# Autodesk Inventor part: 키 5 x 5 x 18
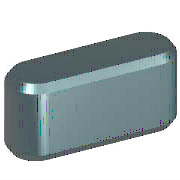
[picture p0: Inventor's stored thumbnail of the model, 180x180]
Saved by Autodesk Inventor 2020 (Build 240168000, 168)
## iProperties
Created: 2012-02
Part Number: 키 5 x 5 x 18
Material: 강철, 연강
Description: 키 및 해당 키홈
Document SubType Name: Modeling
Standard: KS B 1311
Designer: mduedu
Standards Organization: KS
Language: ko-KR
Size Designation: 5 x 5 x 18
Categories: <MemberInstance><Categories><Category DisplayName="샤프트 부품" InternalName="7f7aeb1f-a693-4053-b835-cee3144e0d98" Mnemonic="SHFT"><Category DisplayName="키" Interna
Density: 1 g/cm^3
Appearance: 노란색
IsCustomPart: 1
Author: mduedu
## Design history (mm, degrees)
workplane "Work Plane1"
workplane "Work Plane2"
sketch "스케치1"
  geometry: L1 (2.5, 2.5)-(15.5, 2.5); L2 (15.5, -2.5)-(2.5, -2.5); L3 (0, 9.4)-(0, -7.4) reference; L4 (-5, 0)-(30, 0) reference; L5 (18, 0)-(18, 7); A1 r 2.5 centre (2.5, 0) between (2.5, 2.5) and (2.5, -2.5); A2 r 2.5 centre (15.5, 0) between (15.5, -2.5) and (15.5, 2.5)
  constraints: 6 end point, 5 point on circle, 4 tangent, 3 point on line, 2 centre point, 1 horizontal, 1 parallel, 1 perpendicular
  dimensions: "d0" = 2.5 radius of A1 (= 0.5 x PB); "d13" = 2.5 radius of A2 (= 0.5 x PB); "d14" = 18 distance between parallel lines of L5 L3 (= NLG)
extrude "본체1" new body sketch "스케치1" taper "d3" = 0 deg; stored distance "d4" = 10
workplane "Work Plane3"
body "Solid1"
chamfer "모따기1" distance "d8" = 0.4 (= PHH); stored, may be unused: second distance "d9" = 0.4 (= PHH), angle "d15" = 45 deg
other parameters: "d1" = -3 (= -PNT), "d2" = 2 (= PH - PNT), "NLG" = 18 [user parameter; used in 3 equation terms], "PB" = 5 [user parameter; used in 2 equation terms], "PNT" = 3 [user parameter; used in 2 equation terms], "PH" = 5 [user parameter; used in 1 equation term], "PHH" = 0.4 [user parameter; used in 2 equation terms], "d10" = 0, "d16" = 0, "d17" = 0, "d18" = 0, "WDMIN" = 12 [user parameter], "PLB2" = 18 (= NLG) [user parameter], "WDMAX" = 17 [user parameter], "PLB1" = 18 (= NLG) [user parameter], "RR" = 0.16 [user parameter], "PUEB" = 2.3 [user parameter]
